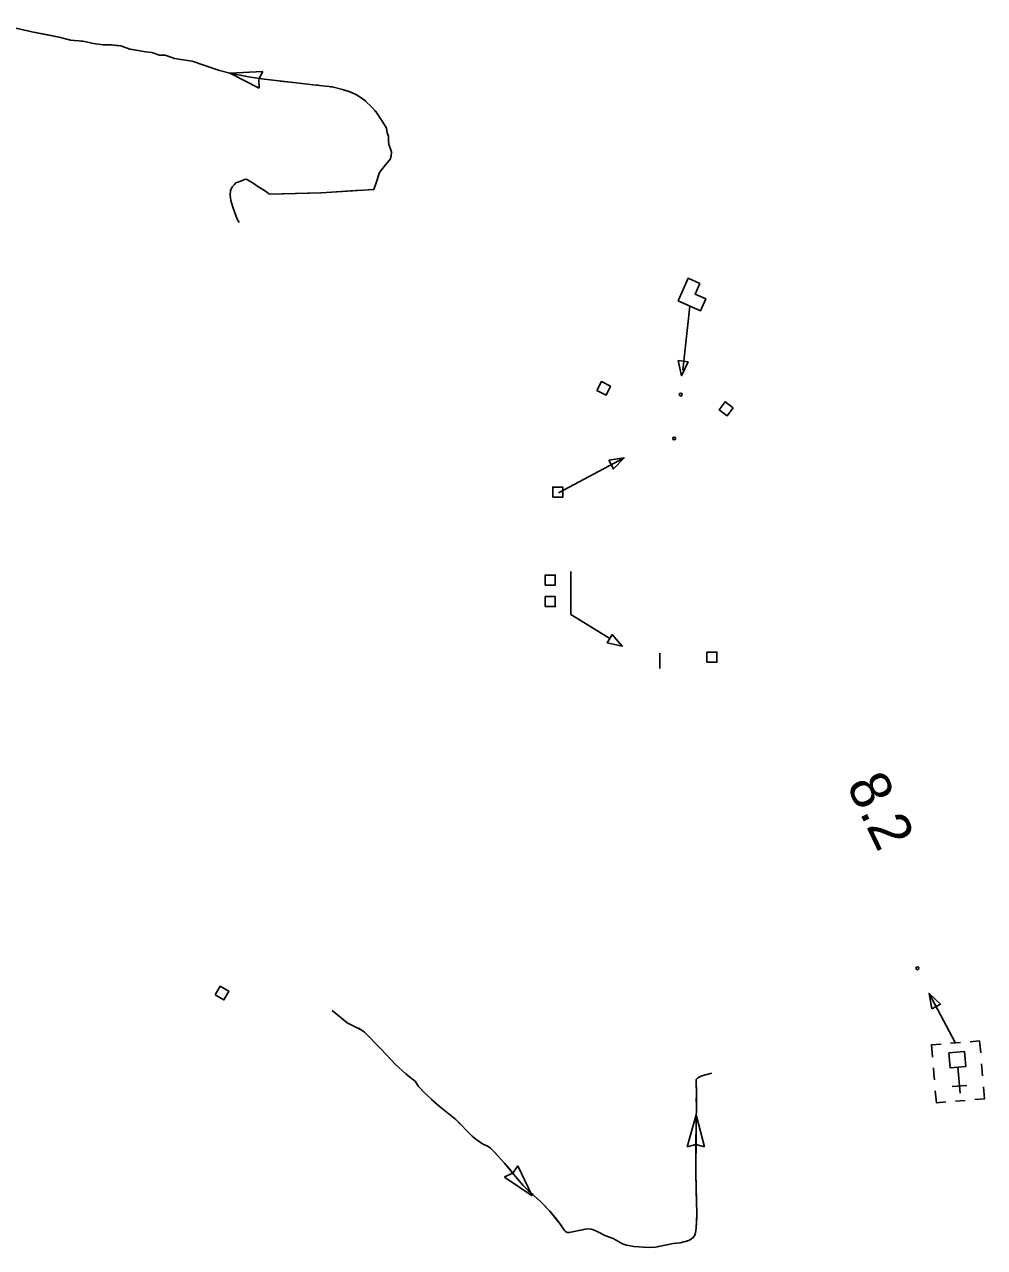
# Model space of a CAD drawing. Extents: x -160 to 6143532, y -375 to 762199.
# Drawn here: x -48.35 to -27.81, y -305.23 to -279.08 of the extents above; entities that cross this region are included whole.
import ezdxf

# ---------------------------------------------------------------- set-up
doc = ezdxf.new("R2010")
doc.units = 0
for name, color, linetype in [('Level 43', 7, 'Continuous'), ('Level 48', 7, 'Continuous'), ('Level 56', 7, 'Continuous'), ('Level 57', 7, 'Continuous'), ('Level 58', 7, 'Continuous')]:
    doc.layers.add(name, color=color, linetype=linetype)

msp = doc.modelspace()

# ---------------------------------------------------------------- linework, layer by layer
at = {"layer": 'Level 43'}
for p, q in [((-43.249, -280.082), (-43.958, -280.117)), ((-43.958, -280.117), (-43.327, -280.441)), ((-43.336, -280.25), (-43.249, -280.082)), ((-43.327, -280.441), (-43.336, -280.253)), ((-33.98, -302.393), (-34.17, -303.077)), ((-33.98, -302.393), (-33.802, -303.08)), ((-34.17, -303.077), (-33.987, -303.03)), ((-33.802, -303.08), (-33.984, -303.03)), ((-38.077, -303.717), (-37.905, -303.64)), ((-37.792, -303.485), (-37.903, -303.638)), ((-37.491, -304.124), (-37.798, -303.484)), ((-37.491, -304.124), (-38.077, -303.724))]:
    msp.add_line(p, q, dxfattribs=at)
for points in [[(-43.755, -283.309), (-43.798, -283.238), (-43.889, -282.984), (-43.93, -282.844), (-43.948, -282.725), (-43.937, -282.628), (-43.904, -282.552), (-43.859, -282.506), (-43.823, -282.466), (-43.719, -282.425), (-43.638, -282.392), (-43.607, -282.387), (-43.577, -282.4), (-43.455, -282.468), (-43.356, -282.545), (-43.216, -282.628), (-43.137, -282.687), (-43.117, -282.707), (-42.007, -282.677), (-40.874, -282.603), (-40.815, -282.445), (-40.754, -282.24), (-40.655, -282.115), (-40.551, -281.993), (-40.518, -281.949), (-40.503, -281.888), (-40.498, -281.81), (-40.521, -281.736), (-40.551, -281.647), (-40.561, -281.566), (-40.561, -281.467), (-40.587, -281.395), (-40.604, -281.291), (-40.681, -281.169), (-40.833, -280.941), (-40.947, -280.816), (-41.1, -280.671), (-41.242, -280.584), (-41.366, -280.523), (-41.547, -280.467), (-41.768, -280.411), (-42.169, -280.365), (-42.654, -280.314), (-43.218, -280.243), (-43.553, -280.197), (-43.952, -280.118), (-44.178, -280.063), (-44.508, -279.946), (-44.762, -279.862), (-45.003, -279.824), (-45.136, -279.803), (-45.336, -279.732), (-45.456, -279.732), (-45.623, -279.679), (-45.76, -279.659), (-45.918, -279.633), (-46.091, -279.605), (-46.284, -279.537), (-46.487, -279.514), (-46.665, -279.511), (-46.873, -279.483), (-47.101, -279.435), (-47.363, -279.415), (-47.576, -279.356), (-48.189, -279.234), (-48.878, -279.077)], [(-47.813, -279.309), (-48.189, -279.234), (-48.215, -279.228)], [(-47.414, -279.401), (-47.576, -279.356), (-47.813, -279.309)], [(-46.332, -279.531), (-46.487, -279.514), (-46.665, -279.511), (-46.873, -279.483), (-47.101, -279.435), (-47.144, -279.432)], [(-45.271, -279.756), (-45.336, -279.732), (-45.456, -279.732), (-45.623, -279.679), (-45.76, -279.659), (-45.918, -279.633), (-46.072, -279.608)], [(-44.222, -280.047), (-44.508, -279.946), (-44.762, -279.862), (-45.003, -279.824), (-45.007, -279.823)], [(-43.151, -280.251), (-43.218, -280.243), (-43.553, -280.197), (-43.952, -280.118), (-43.958, -280.117)], [(-42.066, -280.377), (-42.169, -280.365), (-42.654, -280.314), (-42.88, -280.286)], [(-41.399, -280.512), (-41.547, -280.467), (-41.768, -280.411), (-41.795, -280.408)], [(-41.049, -280.719), (-41.1, -280.671), (-41.242, -280.584), (-41.366, -280.523), (-41.399, -280.512)], [(-40.551, -281.649), (-40.551, -281.647), (-40.561, -281.566), (-40.561, -281.467), (-40.587, -281.395), (-40.604, -281.291), (-40.681, -281.169), (-40.833, -280.941), (-40.858, -280.914)], [(-40.897, -282.605), (-40.874, -282.603), (-40.815, -282.445), (-40.754, -282.24), (-40.655, -282.115), (-40.551, -281.993), (-40.518, -281.949), (-40.509, -281.912)], [(-43.941, -282.662), (-43.937, -282.628), (-43.904, -282.552), (-43.859, -282.506), (-43.823, -282.466), (-43.719, -282.425), (-43.638, -282.392), (-43.607, -282.387), (-43.577, -282.4), (-43.455, -282.468), (-43.356, -282.545), (-43.309, -282.573)], [(-43.079, -282.706), (-42.26, -282.684)], [(-41.987, -282.675), (-41.17, -282.622)], [(-43.755, -283.309), (-43.798, -283.238), (-43.889, -282.984), (-43.905, -282.93)], [(-41.769, -300.164), (-41.443, -300.427), (-41.144, -300.575), (-41.077, -300.626), (-40.717, -300.989), (-40.409, -301.317), (-40.192, -301.519), (-40.078, -301.607), (-39.988, -301.677), (-39.92, -301.789), (-39.801, -301.916), (-39.477, -302.208), (-39.12, -302.497), (-38.77, -302.853), (-38.66, -302.94), (-38.534, -303.023), (-38.429, -303.074), (-38.378, -303.108), (-38.317, -303.169), (-38.077, -303.427), (-37.843, -303.714), (-37.68, -303.904), (-37.573, -304.013), (-37.447, -304.123), (-37.308, -304.249), (-37.109, -304.453), (-36.88, -304.736), (-36.8, -304.867), (-36.778, -304.889), (-36.739, -304.908), (-36.7, -304.911), (-36.622, -304.896), (-36.316, -304.833), (-36.226, -304.84), (-36.175, -304.85), (-36.085, -304.899), (-35.932, -304.977), (-35.756, -305.042), (-35.557, -305.154), (-35.467, -305.181), (-35.314, -305.208), (-35, -305.232), (-34.847, -305.222), (-34.472, -305.144), (-34.324, -305.132), (-34.137, -305.079), (-34.059, -305.035), (-34.015, -304.979), (-33.998, -304.918), (-33.979, -304.816), (-33.964, -304.517), (-33.991, -303.641), (-33.976, -301.94), (-33.977, -301.635), (-33.948, -301.601), (-33.856, -301.562), (-33.647, -301.503)], [(-41.769, -300.164), (-41.45, -300.421)], [(-41.206, -300.544), (-41.144, -300.575), (-41.077, -300.626), (-40.717, -300.989), (-40.612, -301.101)], [(-40.425, -301.3), (-40.409, -301.317), (-40.192, -301.519), (-40.078, -301.607), (-39.988, -301.677), (-39.92, -301.789), (-39.844, -301.87)], [(-33.977, -301.71), (-33.977, -301.635), (-33.948, -301.601), (-33.856, -301.562), (-33.674, -301.511)], [(-33.978, -302.12), (-33.976, -301.94), (-33.977, -301.71)], [(-39.645, -302.056), (-39.477, -302.208), (-39.12, -302.497), (-39.026, -302.592)], [(-33.987, -303.212), (-33.98, -302.393)], [(-38.835, -302.787), (-38.77, -302.853), (-38.66, -302.94), (-38.534, -303.023), (-38.429, -303.074), (-38.378, -303.108), (-38.317, -303.169), (-38.2, -303.294)], [(-38.019, -303.498), (-37.843, -303.714), (-37.68, -303.904), (-37.573, -304.013), (-37.469, -304.103)], [(-33.971, -304.304), (-33.991, -303.641), (-33.989, -303.485)], [(-37.269, -304.289), (-37.109, -304.453), (-36.996, -304.593)], [(-36.996, -304.593), (-36.88, -304.736), (-36.8, -304.867), (-36.778, -304.889), (-36.741, -304.907)], [(-34.381, -305.137), (-34.324, -305.132), (-34.137, -305.079), (-34.059, -305.035), (-34.015, -304.979), (-33.998, -304.918), (-33.979, -304.816), (-33.967, -304.577)], [(-36.473, -304.865), (-36.316, -304.833), (-36.226, -304.84), (-36.175, -304.85), (-36.085, -304.899), (-35.932, -304.977), (-35.756, -305.042), (-35.708, -305.069)], [(-35.461, -305.182), (-35.314, -305.208), (-35, -305.232), (-34.847, -305.222), (-34.65, -305.181)]]:
    msp.add_lwpolyline(points, dxfattribs=at)
at = {"layer": 'Level 56'}
for points in [[(-34.153, -286.288), (-34.362, -286.264), (-34.293, -286.59)], [(-36.102, -286.907), (-36.007, -286.714), (-35.813, -286.809), (-35.908, -287.002)], [(-33.187, -287.272), (-33.314, -287.446), (-33.488, -287.318), (-33.361, -287.144)], [(-35.85, -288.397), (-35.75, -288.583), (-35.521, -288.341)], [(-37.049, -289.186), (-37.049, -288.971), (-36.833, -288.971), (-36.833, -289.186)], [(-37.21, -291.065), (-37.21, -290.85), (-36.994, -290.85), (-36.994, -291.065)], [(-37.21, -291.525), (-37.21, -291.31), (-36.994, -291.31), (-36.994, -291.525)], [(-35.774, -292.119), (-35.885, -292.298), (-35.56, -292.375)], [(-33.751, -292.714), (-33.751, -292.499), (-33.535, -292.499), (-33.535, -292.714)], [(-44.269, -299.829), (-44.16, -299.644), (-43.974, -299.753), (-44.082, -299.938)]]:
    msp.add_lwpolyline(points, close=True, dxfattribs=at)
for points in [[(-35.521, -288.341), (-36.926, -289.09)], [(-35.829, -292.209), (-36.663, -291.692), (-36.663, -290.772)], [(-34.759, -292.848), (-34.759, -292.519)]]:
    msp.add_lwpolyline(points, dxfattribs=at)
msp.add_circle((-34.451, -287.931), 0.031, dxfattribs=at)
at = {"layer": 'Level 57'}
for p, q in [((-28.33, -300.848), (-28.537, -300.865)), ((-27.854, -301.558), (-27.876, -301.3)), ((-28.895, -301.518), (-28.906, -301.388)), ((-28.895, -301.518), (-28.884, -301.645)), ((-28.335, -301.933), (-28.382, -301.378)), ((-28.193, -301.765), (-28.502, -301.791)), ((-28.432, -302.102), (-28.226, -302.084))]:
    msp.add_line(p, q, dxfattribs=at)
for points in [[(-28.998, -299.798), (-28.44, -300.848)], [(-28.742, -300.882), (-28.948, -300.9), (-28.926, -301.158)], [(-27.895, -301.07), (-27.917, -300.813), (-28.123, -300.83)], [(-28.018, -302.067), (-27.812, -302.049), (-27.834, -301.792)], [(-28.637, -302.119), (-28.843, -302.137), (-28.865, -301.879)]]:
    msp.add_lwpolyline(points, dxfattribs=at)
for points in [[(-28.942, -300.127), (-28.756, -300.028), (-28.998, -299.798)], [(-28.575, -301.07), (-28.548, -301.392), (-28.214, -301.363), (-28.242, -301.042)]]:
    msp.add_lwpolyline(points, close=True, dxfattribs=at)
msp.add_circle((-29.248, -299.259), 0.031, dxfattribs=at)
at = {"layer": 'Level 58'}
msp.add_lwpolyline([(-34.367, -284.985), (-33.887, -285.198), (-33.775, -284.944), (-34.002, -284.844), (-33.902, -284.617), (-34.155, -284.505)], close=True, dxfattribs=at)
msp.add_lwpolyline([(-34.267, -286.471), (-34.114, -285.104)], dxfattribs=at)
msp.add_circle((-34.31, -286.992), 0.031, dxfattribs=at)

# ---------------------------------------------------------------- texts
at = {"layer": 'Level 48'}
msp.add_text('8.2', height=0.8737, rotation=295.6641, dxfattribs=at).set_placement((-30.774, -295.338))

doc.saveas('drawing.dxf')
